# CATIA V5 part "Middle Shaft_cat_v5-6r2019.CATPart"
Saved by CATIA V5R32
Part number: Middle shaft
Bounding box of the stored display mesh (mm): x 0 to 100, y -25 to 25, z -24.818 to 24.818
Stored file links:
  D:\PROJECTS\Project 2022\CATIA V5 6R 2022\Resources\Tutorial Files\c16_catia_v5_6r2022_tut\CV joint\Middle Shaft_cat_v5-6r2019.CATPart
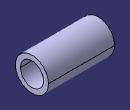
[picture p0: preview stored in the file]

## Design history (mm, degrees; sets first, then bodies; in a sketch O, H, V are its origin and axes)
Body1 (main body)
  Sketch1 on yz-plane, origin (0, 0, 0), H (0, 1, 0), V (0, 0, 1)
    circle A1 centre (0, 0) radius 25
    circle A2 centre (0, 0) radius 17.5
    radius A1 = 25
    radius A2 = 17.5
  Pad1: profile Sketch1, direction (1, 0, 0), length 100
